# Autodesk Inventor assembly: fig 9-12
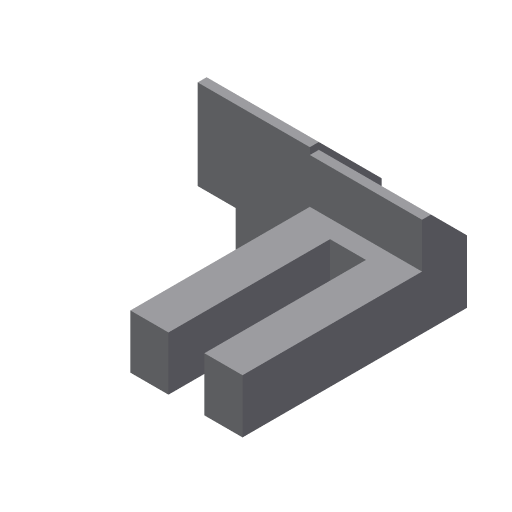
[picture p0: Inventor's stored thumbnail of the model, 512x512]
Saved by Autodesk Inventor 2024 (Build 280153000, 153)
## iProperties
Shininess: 64.0
Length Units: 11269
Angle Units: 11279
Time Units: 11290
Mass Units: 11283
Length Display Precision: 3
Angle Display Precision: 2
Created: 2002-01
Part Number: fig 9-12
Document SubType Name: Assembly
Designer: ***
Density: 0.0
Volumn: 0.0
Area: 0.0
PropertySet Name: Model Information
Control State: 0
Master: False
Checked Out: False
Author: ***
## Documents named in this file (3)
- D:\PROJECTS\Project 2023\RESOURCES INVENTOR 2024\RESOURCES INVENTOR 2024\Inventor_2023_Part\Inventor_2024_Part\c09_Inv_2024_prt\fig 9-12.iam
- D:\PROJECTS\Project 2023\RESOURCES INVENTOR 2024\RESOURCES INVENTOR 2024\Inventor_2023_Part\Inventor_2024_Part\c09_Inv_2024_prt\Part3.ipt
- D:\PROJECTS\Project 2023\RESOURCES INVENTOR 2024\RESOURCES INVENTOR 2024\Inventor_2023_Part\Inventor_2024_Part\c09_Inv_2024_prt\Part4.ipt
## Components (2 placed, 2 different names)
1. Part3:1 — Flush:1, Flush:2, Flush:3, Mate:1
2. Part4:1 — Flush:1, Flush:2, Flush:3, Mate:1
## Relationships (4: Flush 3, Mate 1)
- Flush:1: Part3:1 ↔ Part4:1
- Flush:2: Part3:1 ↔ Part4:1
- Flush:3: Part3:1 ↔ Part4:1
- Mate:1: Part3:1 ↔ Part4:1
